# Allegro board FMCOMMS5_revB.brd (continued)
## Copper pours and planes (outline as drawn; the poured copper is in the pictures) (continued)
VADJ on BOTTOM: 52.44,73.79 52.54,73.89 55.2,73.89 59.13,77.82 62.97,77.82 63.11,77.68 63.11,76.15 62.95,75.98 59.33,75.98 56.12,72.77 56.12,72.77 55.5,72.15 52.56,72.15 52.44,72.27

Small or netless copper shapes (teardrops, artwork), in the pictures only: 20 on BOTTOM

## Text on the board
BOTTOM: 10
Board Geometry/Soldermask Bottom: 08-      -06
Ref Des/Silkscreen Bottom: ENABLE_B | TXNRX_A | CTRL_OUT7_A | CTRL_OUT5_A | CTRL_OUT3_A | CTRL_OUT1_A | GPO0_A | ENABLE_A | TXNRX_B | EN_AGC_A | CTRL_OUT7_B | EN_AGC_B | CTRL_OUT5_B | CTRL_OUT6_A | CTRL_OUT6_B | CTRL_OUT4_B | CTRL_OUT3_B | CTRL_OUT4_A | CTRL_OUT1_B | CTRL_OUT2_A | CTRL_OUT2_B | CTRL_OUT0_A | GPO0_B | CTRL_OUT0_B | GPO2_B | GPO1_A | GPO1_B | GPO2_A | CLK_OUT_A | GPO3_A | GPO3_B | CLK_OUT_B | CTRL_IN2_A | CTRL_IN3_A | CTRL_IN3_B | CTRL_IN2_B | CTRL_IN0_A | CTRL_IN1_A | CTRL_IN1_B | CTRL_IN0_B | AUXDAC1_A | AUXDAC_A | AUXDAC1_B | AUXDAC_B | AUXDAC2_A | SYNC_IN | AUXDAC2_B | GND_PWR | RESET_A | RESET_B | RX2A_A | TX2A_A | TX1A_B | RX1B_B | RX2B_A | RX1A_B | REF_CLK_IN | EXT_LO_IN | TX_MON1_B | RX2B_B | RX1B_A | RX2A_B | RX1A_A | TX2A_B | TX1A_A | TX_MON2_B | TX_MON1_A | TX_MON2_A | AD-FMCOMMS5-EBZ | 08-      -05
User.Comments: R. REEDER | 11MAR13 | B | MODIFIED POWER SECTION | 05AUG13 | J.D.B.
TOP: 1
Board Geometry/Soldermask Top: 08-      -04
Ref Des/Silkscreen Top: GND_PWR | 12_V | 3P3v | TXNRX_B | CTRL_OUT7_B | CTRL_OUT5_B | CTRL_OUT3_B | CTRL_OUT1_B | GPO0_B | GPO2_B | CLK_OUT_B | CTRL_IN2_B | CTRL_IN0_B | AUXDAC1_B | SYNC_IN | TXNRX_A | ENABLE_A | ENABLE_B | EN_AGC_A | CTRL_OUT7_A | EN_AGC_B | CTRL_OUT5_A | CTRL_OUT6_A | CTRL_OUT6_B | CTRL_OUT4_A | CTRL_OUT4_B | CTRL_OUT3_A | CTRL_OUT1_A | CTRL_OUT2_A | CTRL_OUT2_B | CTRL_OUT0_A | GPO0_A | CTRL_OUT0_B | GPO2_A | GPO1_A | GPO1_B | GPO3_A | GPO3_B | CLK_OUT_A | CTRL_IN3_A | CTRL_IN3_B | CTRL_IN2_A | CTRL_IN1_A | CTRL_IN1_B | CTRL_IN0_A | AUXDAC_A | AUXDAC_B | AUXDAC1_A | AUXDAC2_A | AUXDAC2_B | RESET_A | RESET_B | REF_CLK_IN | RX1B_B | RX2A_A | TX2A_A | TX1A_B | RX2B_A | RX1A_B | EXT_LO_IN | TX_MON1_B | RX1B_A | RX2B_B | RX1A_A | RX2A_B | TX2A_B | TX1A_A | TX_MON2_B | TX_MON1_A | TX_MON2_A | 08-      -03
L2_GND: 2
L3_PWR: 3
L4_GND: 4
L5_SIG: 5
L6_SIG: 6
L7_GND: 7
L8_PWR: 8
L9_GND: 9
DIMENSION: 15.    THRU VIAS FILLED WITH NON-CONDUCTIVE EPOXY AND PLATED OVER. | COPLANAR ON BOTH SIDES WITHIN .001 INCH PRIOR TO FINAL PLATING | (0,0) | SEE NOTE 15
PAGE_OUTLINE: 24FEB14 | B | AS PER ECR-046703 | 09JUN14 | W TAYLOR
BODY_CENTER: 08-      -01
DISPLAY_BOTTOM: 08-      -02
DISPLAY_TOP: 08-      -17
User.6: 08-      -18
User.7: 08-      -15
User.8: 08-      -16
User.17: CHARACTERISTIC IMPEDANCE = 100 OHMS +/- 10% DIFFERENTIAL PAIRS | ARTWORK LINE WIDTH FOR | IMPEDANCE CONTROLLED LINES = 0.0038"/0.0062" | CHARACTERISTIC IMPEDANCE = 50 OHMS +/- 10% SINGLE ENDED | IMPEDANCE CONTROLLED LINES = 0.0155" AND 0.0049"
User.20: L2 GND | 08-      -07
User.21: L3 PWR | 08-      -08
User.22: L4 GND | 08-      -09
User.23: L5 SIG | 08-      -10
User.24: L6 SIG | 08-      -11
User.25: L7 GND | 08-      -12
User.26: L8 PWR | 08-      -13
User.27: L9 GND | 08-      -14
User.35: FIGURE | SIZE | 6.0 | 8.0 | 10.0 | 10.01 | 20.0 | 40.0 | 45.0 | 60.0 | 105.0 | 50.0 | PLATED | NON-PLATED | FINISHED HOLES IN MILS | ALL UNITS ARE IN MILS | QTY | 254 | 323 | 1011 | 97 | 306 | 3 | 52 | 5 | 4 | TOLERANCE/NOTES
